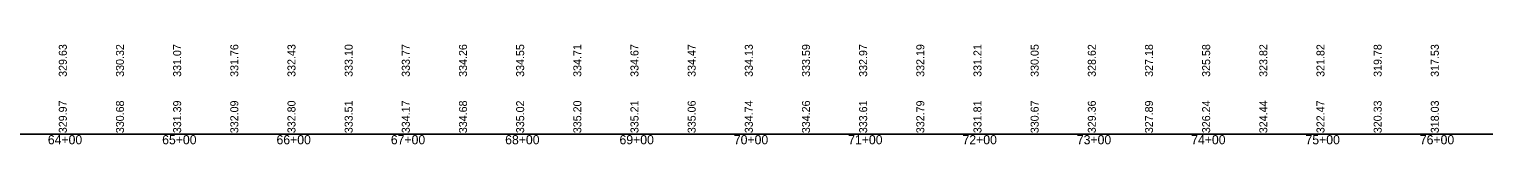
# Model space of a CAD drawing. Extents: x 1876258 to 1926563, y 729739 to 834437.
# Drawn here: x 1884729 to 1886002, y 830495 to 830583 of the extents above; entities that cross this region are included whole.
import ezdxf

# ---------------------------------------------------------------- set-up
doc = ezdxf.new("R2010")
doc.units = 0
for name, color, linetype in [('RD_EX_RailRoad', 7, 'Continuous'), ('RD_PD_ALT3_CL', 7, 'Continuous'), ('RD_PD_Final_Cl', 7, 'Continuous')]:
    doc.layers.add(name, color=color, linetype=linetype)

msp = doc.modelspace()

# ---------------------------------------------------------------- linework, layer by layer
at = {"layer": 'RD_PD_Final_Cl'}
msp.add_line((1878363.1, 830504.3), (1926563.1, 830504.3), dxfattribs=at)

# ---------------------------------------------------------------- texts
at = {"layer": 'RD_EX_RailRoad'}
for s, p in [('329.63', (1884762.1, 830554.3)), ('330.32', (1884812.1, 830554.3)), ('331.07', (1884862.1, 830554.3)), ('331.76', (1884912.1, 830554.3)), ('332.43', (1884962.1, 830554.3)), ('333.10', (1885012.1, 830554.3)), ('333.77', (1885062.1, 830554.3)), ('334.26', (1885112.1, 830554.3)), ('334.55', (1885162.1, 830554.3)), ('334.71', (1885212.1, 830554.3)), ('334.67', (1885262.1, 830554.3)), ('334.47', (1885312.1, 830554.3)), ('334.13', (1885362.1, 830554.3)), ('333.59', (1885412.1, 830554.3)), ('332.97', (1885462.1, 830554.3)), ('332.19', (1885512.1, 830554.3)), ('331.21', (1885562.1, 830554.3)), ('330.05', (1885612.1, 830554.3)), ('328.62', (1885662.1, 830554.3)), ('327.18', (1885712.1, 830554.3)), ('325.58', (1885762.1, 830554.3)), ('323.82', (1885812.1, 830554.3)), ('321.82', (1885862.1, 830554.3)), ('319.78', (1885912.1, 830554.3)), ('317.53', (1885962.1, 830554.3)), ('329.97', (1884762.1, 830505)), ('330.68', (1884812.1, 830505)), ('331.39', (1884862.1, 830505)), ('332.09', (1884912.1, 830505)), ('332.80', (1884962.1, 830505)), ('333.51', (1885012.1, 830505)), ('334.17', (1885062.1, 830505)), ('334.68', (1885112.1, 830505)), ('335.02', (1885162.1, 830505)), ('335.20', (1885212.1, 830505)), ('335.21', (1885262.1, 830505)), ('335.06', (1885312.1, 830505)), ('334.74', (1885362.1, 830505)), ('334.26', (1885412.1, 830505)), ('333.61', (1885462.1, 830505)), ('332.79', (1885512.1, 830505)), ('331.81', (1885562.1, 830505)), ('330.67', (1885612.1, 830505)), ('329.36', (1885662.1, 830505)), ('327.89', (1885712.1, 830505)), ('326.24', (1885762.1, 830505)), ('324.44', (1885812.1, 830505)), ('322.47', (1885862.1, 830505)), ('320.33', (1885912.1, 830505)), ('318.03', (1885962.1, 830505))]:
    msp.add_text(s, height=7, rotation=90, dxfattribs=at).set_placement(p)
at = {"layer": 'RD_PD_ALT3_CL'}
for s, p in [('64+00', (1884745.5, 830495.3)), ('64+00', (1884745.5, 830495.3)), ('65+00', (1884845.5, 830495.3)), ('65+00', (1884845.5, 830495.3)), ('66+00', (1884945.5, 830495.3)), ('66+00', (1884945.5, 830495.3)), ('67+00', (1885045.5, 830495.3)), ('67+00', (1885045.5, 830495.3)), ('68+00', (1885145.5, 830495.3)), ('68+00', (1885145.5, 830495.3)), ('69+00', (1885245.5, 830495.3)), ('69+00', (1885245.5, 830495.3)), ('70+00', (1885345.5, 830495.3)), ('70+00', (1885345.5, 830495.3)), ('71+00', (1885445.5, 830495.3)), ('71+00', (1885445.5, 830495.3)), ('72+00', (1885545.5, 830495.3)), ('72+00', (1885545.5, 830495.3)), ('73+00', (1885645.5, 830495.3)), ('73+00', (1885645.5, 830495.3)), ('74+00', (1885745.5, 830495.3)), ('74+00', (1885745.5, 830495.3)), ('75+00', (1885845.5, 830495.3)), ('75+00', (1885845.5, 830495.3)), ('76+00', (1885945.5, 830495.3)), ('76+00', (1885945.5, 830495.3))]:
    msp.add_text(s, height=8, dxfattribs=at).set_placement(p)

doc.saveas('drawing.dxf')
